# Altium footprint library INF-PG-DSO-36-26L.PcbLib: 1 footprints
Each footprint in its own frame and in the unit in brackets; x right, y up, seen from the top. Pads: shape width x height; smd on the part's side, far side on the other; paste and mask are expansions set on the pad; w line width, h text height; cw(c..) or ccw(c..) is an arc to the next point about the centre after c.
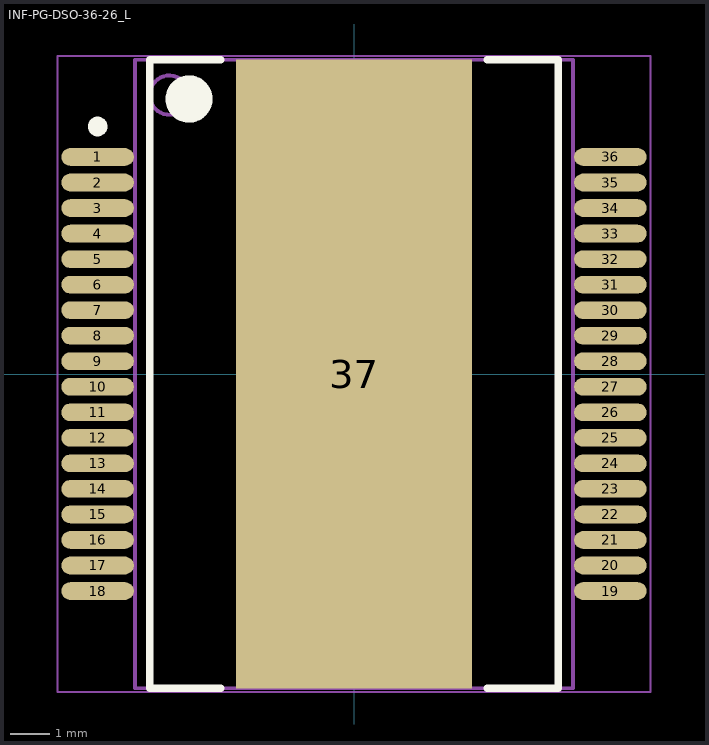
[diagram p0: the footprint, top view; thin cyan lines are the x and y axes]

## INF-PG-DSO-36-26_L [mm] "SOP, 36-Leads, Body 15.9x11mm, Pitch 0.65mm, Thermal Pad 16x6mm, IPC High Density"
height 3.5
pads (37):
  oval 1.85x0.45 smd: 1(-6.525,5.525) 2(-6.525,4.875) 3(-6.525,4.225) 4(-6.525,3.575) 5(-6.525,2.925) 6(-6.525,2.275) 7(-6.525,1.625) 8(-6.525,0.975) 9(-6.525,0.325) 10(-6.525,-0.325) 11(-6.525,-0.975) 12(-6.525,-1.625) 13(-6.525,-2.275) 14(-6.525,-2.925) 15(-6.525,-3.575) 16(-6.525,-4.225) 17(-6.525,-4.875) 18(-6.525,-5.525) 19(6.525,-5.525) 20(6.525,-4.875) 21(6.525,-4.225) 22(6.525,-3.575) 23(6.525,-2.925) 24(6.525,-2.275) 25(6.525,-1.625) 26(6.525,-0.975) 27(6.525,-0.325) 28(6.525,0.325) 29(6.525,0.975) 30(6.525,1.625) 31(6.525,2.275) 32(6.525,2.925) 33(6.525,3.575) 34(6.525,4.225) 35(6.525,4.875) 36(6.525,5.525)
  rect 6x16 smd: 37(0,0)
Top Overlay:
  circle w0.6: c-4.2,7 r0.3
  circle w0.25: c-6.525,6.3 r0.125
  lines w0.2: -3.4,-8 -5.2,-8 -5.2,8 -3.4,8 ; 3.4,-8 5.2,-8 5.2,8 3.4,8
Mechanical 13:
  circle w0.1: c-4.7,7.1 r0.5
  lines w0.1: -5.575,-8 5.575,-8 5.575,8 -5.575,8 -5.575,-8
Mechanical 15:
  lines w0.05: -7.55,-8.1 7.55,-8.1 7.55,8.1 -7.55,8.1 -7.55,-8.1
  lines w0.1: -0.5,0 0.5,0 ; 0,-0.5 0,0.5
3D body: height 3.5, standoff 0, extent -5.575,-8 5.575,8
